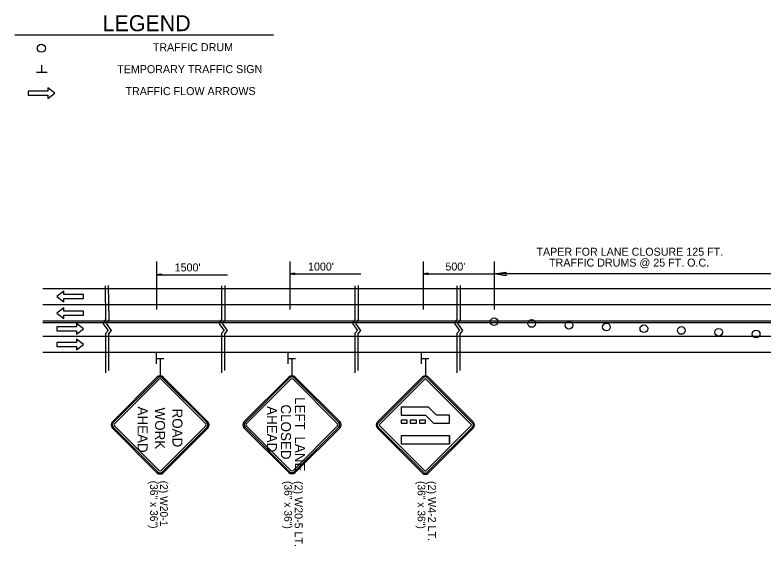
# Model space of a CAD drawing. Extents: x 1930579 to 1937984, y 596452 to 597630.
# Drawn here: x 1936432 to 1936993, y 597218 to 597617 of the extents above; entities that cross this region are included whole.
import ezdxf

# ---------------------------------------------------------------- set-up
doc = ezdxf.new("R2010")
doc.units = 0
for name, color, linetype in [('Default', 7, 'Continuous'), ('P_TC_Signs_Permanent', 7, 'Continuous'), ('P_TC_Signs_Temporary', 7, 'Continuous'), ('R_Annotation', 7, 'Continuous'), ('R_MOT', 7, 'Continuous'), ('R_Striping', 7, 'Continuous')]:
    doc.layers.add(name, color=color, linetype=linetype)

msp = doc.modelspace()

# ---------------------------------------------------------------- linework, layer by layer
at = {"layer": 'Default'}
for p, q in [((1936537.79, 597431.71), (1936537.79, 597395.8)), ((1936637.79, 597431.71), (1936637.79, 597395.8)), ((1936737.79, 597431.71), (1936737.79, 597395.8)), ((1936791.02, 597431.71), (1936791.02, 597395.8)), ((1936541.62, 597422.3), (1936537.79, 597421.72)), ((1936537.79, 597421.72), (1936591.02, 597421.72)), ((1936541.62, 597421.15), (1936537.79, 597421.72)), ((1936541.62, 597422.2), (1936538.43, 597421.72)), ((1936541.62, 597421.24), (1936538.43, 597421.72)), ((1936541.62, 597422.1), (1936539.09, 597421.72)), ((1936541.62, 597421.34), (1936539.09, 597421.72)), ((1936541.62, 597422.01), (1936539.73, 597421.72)), ((1936541.62, 597421.44), (1936539.73, 597421.72)), ((1936541.62, 597421.91), (1936540.37, 597421.72)), ((1936541.62, 597421.54), (1936540.37, 597421.72)), ((1936541.62, 597421.81), (1936541.01, 597421.72)), ((1936541.62, 597421.63), (1936541.01, 597421.72)), ((1936541.62, 597421.15), (1936541.62, 597422.3)), ((1936641.62, 597422.98), (1936637.79, 597422.4)), ((1936637.79, 597422.4), (1936691.02, 597422.4)), ((1936641.62, 597421.83), (1936637.79, 597422.4)), ((1936641.62, 597422.88), (1936638.43, 597422.4)), ((1936641.62, 597421.92), (1936638.43, 597422.4)), ((1936641.62, 597422.78), (1936639.09, 597422.4)), ((1936641.62, 597422.02), (1936639.09, 597422.4)), ((1936641.62, 597422.69), (1936639.73, 597422.4)), ((1936641.62, 597422.12), (1936639.73, 597422.4)), ((1936641.62, 597422.59), (1936640.37, 597422.4)), ((1936641.62, 597422.22), (1936640.37, 597422.4)), ((1936641.62, 597422.49), (1936641.01, 597422.4)), ((1936641.62, 597422.31), (1936641.01, 597422.4)), ((1936641.62, 597421.83), (1936641.62, 597422.98)), ((1936741.62, 597422.98), (1936737.79, 597422.4)), ((1936737.79, 597422.4), (1936791.02, 597422.4)), ((1936741.62, 597421.83), (1936737.79, 597422.4)), ((1936741.62, 597422.88), (1936738.43, 597422.4)), ((1936741.62, 597421.92), (1936738.43, 597422.4)), ((1936741.62, 597422.78), (1936739.09, 597422.4)), ((1936741.62, 597422.02), (1936739.09, 597422.4)), ((1936741.62, 597422.69), (1936739.73, 597422.4)), ((1936741.62, 597422.12), (1936739.73, 597422.4)), ((1936741.62, 597422.59), (1936740.37, 597422.4)), ((1936741.62, 597422.22), (1936740.37, 597422.4)), ((1936741.62, 597422.49), (1936741.01, 597422.4)), ((1936741.62, 597422.31), (1936741.01, 597422.4)), ((1936741.62, 597421.83), (1936741.62, 597422.98)), ((1936791.02, 597422.4), (1936799.89, 597423.73)), ((1937015.53, 597422.4), (1936791.02, 597422.4)), ((1936799.89, 597421.07), (1936791.02, 597422.4)), ((1936799.89, 597423.73), (1936799.89, 597421.07)), ((1937804.86, 597411.17), (1936452.69, 597411.17)), ((1937804.86, 597399.17), (1936452.69, 597399.17)), ((1937804.86, 597386.94), (1936452.69, 597386.94)), ((1937804.86, 597385.79), (1936452.69, 597385.79)), ((1937804.86, 597375.6), (1936452.69, 597375.6)), ((1937804.86, 597363.6), (1936452.69, 597363.6)), ((1936537.79, 597355), (1936537.79, 597362.98)), ((1936537.91, 597358.97), (1936543.36, 597358.97)), ((1936636.62, 597354.95), (1936636.62, 597362.93)), ((1936636.74, 597358.92), (1936642.18, 597358.92)), ((1936736.62, 597354.95), (1936736.62, 597362.93)), ((1936736.74, 597358.92), (1936742.18, 597358.92))]:
    msp.add_line(p, q, dxfattribs=at)
for points in [[(1936499.33, 597413.45), (1936499.72, 597388.21), (1936497.77, 597385.31), (1936501.57, 597380.12), (1936499.57, 597377.72), (1936499.56, 597348.37)], [(1936501.73, 597413.68), (1936502.12, 597388.11), (1936500.17, 597385.21), (1936503.96, 597380.02), (1936501.96, 597377.62), (1936501.96, 597350.06)], [(1936586.69, 597413.45), (1936586.69, 597388.21), (1936584.74, 597385.31), (1936588.54, 597380.12), (1936586.54, 597377.72), (1936586.54, 597348.37)], [(1936589.09, 597413.68), (1936589.09, 597388.11), (1936587.14, 597385.21), (1936590.94, 597380.02), (1936588.94, 597377.62), (1936588.94, 597350.06)], [(1936686.69, 597413.45), (1936686.69, 597388.21), (1936684.74, 597385.31), (1936688.54, 597380.12), (1936686.54, 597377.72), (1936686.54, 597348.37)], [(1936689.09, 597413.68), (1936689.09, 597388.11), (1936687.14, 597385.21), (1936690.94, 597380.02), (1936688.94, 597377.62), (1936688.94, 597350.06)], [(1936763.16, 597413.45), (1936763.16, 597388.21), (1936761.21, 597385.31), (1936765.01, 597380.12), (1936763.01, 597377.72), (1936763, 597348.37)], [(1936765.56, 597413.68), (1936765.56, 597388.11), (1936763.61, 597385.21), (1936767.4, 597380.02), (1936765.41, 597377.62), (1936765.4, 597350.06)]]:
    msp.add_lwpolyline(points, dxfattribs=at)
for centre, radius in [((1936451.57, 597591.57), 3), ((1936791.02, 597386.59), 2.87), ((1936819.09, 597385.28), 2.87), ((1936847.15, 597383.97), 2.87), ((1936875.21, 597382.65), 2.87), ((1936903.28, 597381.34), 2.87), ((1936931.34, 597380.03), 2.87), ((1936959.4, 597378.71), 2.87), ((1936987.47, 597377.4), 2.87)]:
    msp.add_circle(centre, radius, dxfattribs=at)
at = {"layer": 'P_TC_Signs_Permanent'}
for p, q in [((1936737.34, 597345.24), (1936703.4, 597311.3)), ((1936775.52, 597311.3), (1936741.58, 597345.24)), ((1936703.4, 597307.05), (1936737.34, 597273.11)), ((1936757.46, 597301.13), (1936757.46, 597295.13))]:
    msp.add_line(p, q, dxfattribs=at)
for points in [[(1936704.03, 597310.66), (1936737.97, 597344.6)], [(1936739.04, 597343.54), (1936705.09, 597309.6)], [(1936773.82, 597309.6), (1936739.88, 597343.54)], [(1936740.94, 597344.6), (1936774.89, 597310.66)], [(1936737.97, 597273.75), (1936704.03, 597307.69)], [(1936705.09, 597308.75), (1936739.04, 597274.81)], [(1936739.88, 597274.81), (1936773.82, 597308.75)], [(1936774.89, 597307.69), (1936740.94, 597273.75)], [(1936741.58, 597273.11), (1936758.55, 597290.08), (1936775.52, 597307.05)]]:
    msp.add_lwpolyline(points, dxfattribs=at)
for points in [[(1936721.46, 597322.67), (1936721.46, 597316.67), (1936739.46, 597316.67), (1936745.46, 597310.67), (1936757.46, 597310.67), (1936757.46, 597316.67), (1936747.94, 597316.67), (1936741.94, 597322.67)], [(1936721.46, 597312.77), (1936721.46, 597310.67), (1936725.96, 597310.67), (1936725.96, 597312.77)], [(1936728.21, 597312.77), (1936728.21, 597310.67), (1936732.71, 597310.67), (1936732.71, 597312.77)], [(1936734.96, 597312.77), (1936734.96, 597310.67), (1936739.46, 597310.67), (1936739.46, 597312.77)], [(1936721.46, 597301.13), (1936721.46, 597295.13), (1936757.46, 597295.13), (1936757.46, 597301.13)]]:
    msp.add_lwpolyline(points, close=True, dxfattribs=at)
for centre, radius, start, end in [((1936739.46, 597343.12), 3, 45, 135), ((1936739.46, 597343.12), 2.1, 45, 135), ((1936739.46, 597343.12), 0.6, 45, 135), ((1936705.52, 597309.17), 3, 135, 225), ((1936705.52, 597309.17), 2.1, 135, 225), ((1936705.52, 597309.17), 0.6, 135, 225), ((1936773.4, 597309.17), 0.6, 315, 45), ((1936773.4, 597309.17), 2.1, 315, 45), ((1936773.4, 597309.17), 3, 315, 45), ((1936739.46, 597275.23), 0.6, 225, 315), ((1936739.46, 597275.23), 3, 225, 315), ((1936739.46, 597275.23), 2.1, 225, 315)]:
    msp.add_arc(centre, radius, start, end, dxfattribs=at)
at = {"layer": 'P_TC_Signs_Temporary'}
for p, q in [((1936504.84, 597311.64), (1936538.25, 597345.05)), ((1936505.5, 597310.98), (1936538.91, 597344.39)), ((1936506.43, 597310.05), (1936539.84, 597343.46)), ((1936541.43, 597343.46), (1936574.84, 597310.05)), ((1936542.36, 597344.39), (1936575.77, 597310.98)), ((1936543.02, 597345.05), (1936576.43, 597311.64)), ((1936603.66, 597311.72), (1936637.07, 597345.13)), ((1936604.33, 597311.05), (1936637.74, 597344.46)), ((1936605.25, 597310.13), (1936638.66, 597343.54)), ((1936640.26, 597343.54), (1936673.67, 597310.13)), ((1936641.18, 597344.46), (1936674.59, 597311.05)), ((1936641.85, 597345.13), (1936675.26, 597311.72)), ((1936538.91, 597274.12), (1936505.5, 597307.53)), ((1936539.84, 597275.05), (1936506.43, 597308.46)), ((1936574.84, 597308.46), (1936541.43, 597275.05)), ((1936575.77, 597307.53), (1936542.36, 597274.12)), ((1936637.74, 597274.2), (1936604.33, 597307.61)), ((1936638.66, 597275.12), (1936605.25, 597308.53)), ((1936673.67, 597308.53), (1936640.26, 597275.12)), ((1936674.59, 597307.61), (1936641.18, 597274.2)), ((1936538.25, 597273.46), (1936504.84, 597306.87)), ((1936576.43, 597306.87), (1936543.02, 597273.46)), ((1936637.07, 597273.53), (1936603.66, 597306.94)), ((1936675.26, 597306.94), (1936641.85, 597273.53))]:
    msp.add_line(p, q, dxfattribs=at)
for centre, radius, start, end in [((1936540.63, 597342.67), 3.38, 45, 135), ((1936540.63, 597342.67), 2.44, 45, 135), ((1936540.63, 597342.67), 1.12, 45, 135), ((1936639.46, 597342.74), 3.38, 45, 135), ((1936639.46, 597342.74), 2.44, 45, 135), ((1936639.46, 597342.74), 1.12, 45, 135), ((1936507.22, 597309.26), 3.38, 135, 225), ((1936507.22, 597309.26), 2.44, 135, 225), ((1936507.22, 597309.26), 1.13, 135, 225), ((1936574.04, 597309.26), 1.13, 315, 45), ((1936574.04, 597309.26), 2.44, 315, 45), ((1936574.04, 597309.26), 3.38, 315, 45), ((1936606.05, 597309.33), 3.38, 135, 225), ((1936606.05, 597309.33), 2.44, 135, 225), ((1936606.05, 597309.33), 1.13, 135, 225), ((1936672.87, 597309.33), 1.13, 315, 45), ((1936672.87, 597309.33), 2.44, 315, 45), ((1936672.87, 597309.33), 3.38, 315, 45), ((1936540.63, 597275.85), 2.44, 225, 315), ((1936540.63, 597275.85), 1.12, 225, 315), ((1936639.46, 597275.92), 2.44, 225, 315), ((1936639.46, 597275.92), 1.12, 225, 315), ((1936540.63, 597275.85), 3.38, 225, 315), ((1936639.46, 597275.92), 3.38, 225, 315)]:
    msp.add_arc(centre, radius, start, end, dxfattribs=at)
at = {"layer": 'R_Annotation'}
for p, q in [((1936431.79, 597601.6), (1936625.71, 597601.73)), ((1936451.95, 597573.4), (1936451.95, 597578.86)), ((1936455.93, 597573.29), (1936447.93, 597573.28)), ((1936540.63, 597358.97), (1936540.63, 597346.04)), ((1936639.46, 597358.91), (1936639.46, 597346.12)), ((1936739.46, 597358.91), (1936739.46, 597346.12))]:
    msp.add_line(p, q, dxfattribs=at)
at = {"layer": 'R_MOT'}
msp.add_lwpolyline([(1936456.44, 597553.89), (1936461.63, 597557.89), (1936456.44, 597561.89), (1936456.44, 597559.39), (1936441.73, 597559.38), (1936441.73, 597556.38), (1936456.44, 597556.39)], close=True, dxfattribs=at)
at = {"layer": 'R_Striping'}
for points in [[(1936468.42, 597409.53), (1936463.23, 597405.53), (1936468.42, 597401.53), (1936468.42, 597404.03), (1936483.13, 597404.03), (1936483.13, 597407.03), (1936468.42, 597407.03)], [(1936468.42, 597396.9), (1936463.23, 597392.9), (1936468.42, 597388.9), (1936468.42, 597391.4), (1936483.13, 597391.4), (1936483.13, 597394.4), (1936468.42, 597394.4)], [(1936477.94, 597377.39), (1936483.13, 597381.39), (1936477.94, 597385.39), (1936477.94, 597382.89), (1936463.23, 597382.89), (1936463.23, 597379.89), (1936477.94, 597379.89)], [(1936477.94, 597365.61), (1936483.13, 597369.61), (1936477.94, 597373.61), (1936477.94, 597371.11), (1936463.23, 597371.11), (1936463.23, 597368.11), (1936477.94, 597368.11)]]:
    msp.add_lwpolyline(points, close=True, dxfattribs=at)

# ---------------------------------------------------------------- texts
at = {"layer": 'Default'}
for s, p in [('TAPER FOR LANE CLOSURE 125 FT.', (1936822.78, 597436.06)), ("1000'", (1936651.51, 597424.96)), ("500'", (1936754.51, 597424.96)), ('TRAFFIC DRUMS @ 25 FT. O.C.', (1936832.22, 597427.9)), ("1500'", (1936551.51, 597424.3))]:
    msp.add_text(s, height=6, rotation=360, dxfattribs=at).set_placement(p)
at = {"layer": 'P_TC_Signs_Temporary'}
for s, p in [('LEFT\u2002LANE', (1936641.71, 597330.13)), (' AHEAD ', (1936523.8, 597325.8)), ('WORK', (1936536.82, 597322.25)), (' ROAD ', (1936549.85, 597324.28)), (' AHEAD ', (1936620.71, 597326.1)), ('CLOSED', (1936631.21, 597324.58))]:
    msp.add_text(s, height=7.5, rotation=270, dxfattribs=at).set_placement(p)
at = {"layer": 'R_Annotation'}
for s, height, rotation, p in [('LEGEND', 12, 0.0388, (1936497.52, 597604.33)), ('TRAFFIC DRUM', 6, 0.0388, (1936535.11, 597589.37)), ('TEMPORARY TRAFFIC SIGN', 6, 0.0388, (1936508.44, 597572.89)), ('TRAFFIC FLOW ARROWS', 6, 0.0388, (1936514.64, 597556.43)), ('(36" x 36")', 5.76, 270, (1936533.14, 597267.47)), ('(2) W20-1', 5.76, 270, (1936540.63, 597267.47)), ('(36" x 36")', 5.76, 270, (1936633.7, 597267.23)), ('(2) W20-5 LT.', 6, 270, (1936641.47, 597267.23)), ('(36" x 36")', 5.76, 270, (1936733.7, 597267.23)), ('(2) W4-2 LT.', 6, 270, (1936741.47, 597267.23))]:
    msp.add_text(s, height=height, rotation=rotation, dxfattribs=at).set_placement(p)

doc.saveas('drawing.dxf')
